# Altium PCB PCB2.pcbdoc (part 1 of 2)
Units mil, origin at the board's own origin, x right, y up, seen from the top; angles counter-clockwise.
Board outline 4920 x 2460 mil, 2 copper layers (Top Layer, Bottom Layer); 93 components, 68 nets, 331 pads, 95 vias.
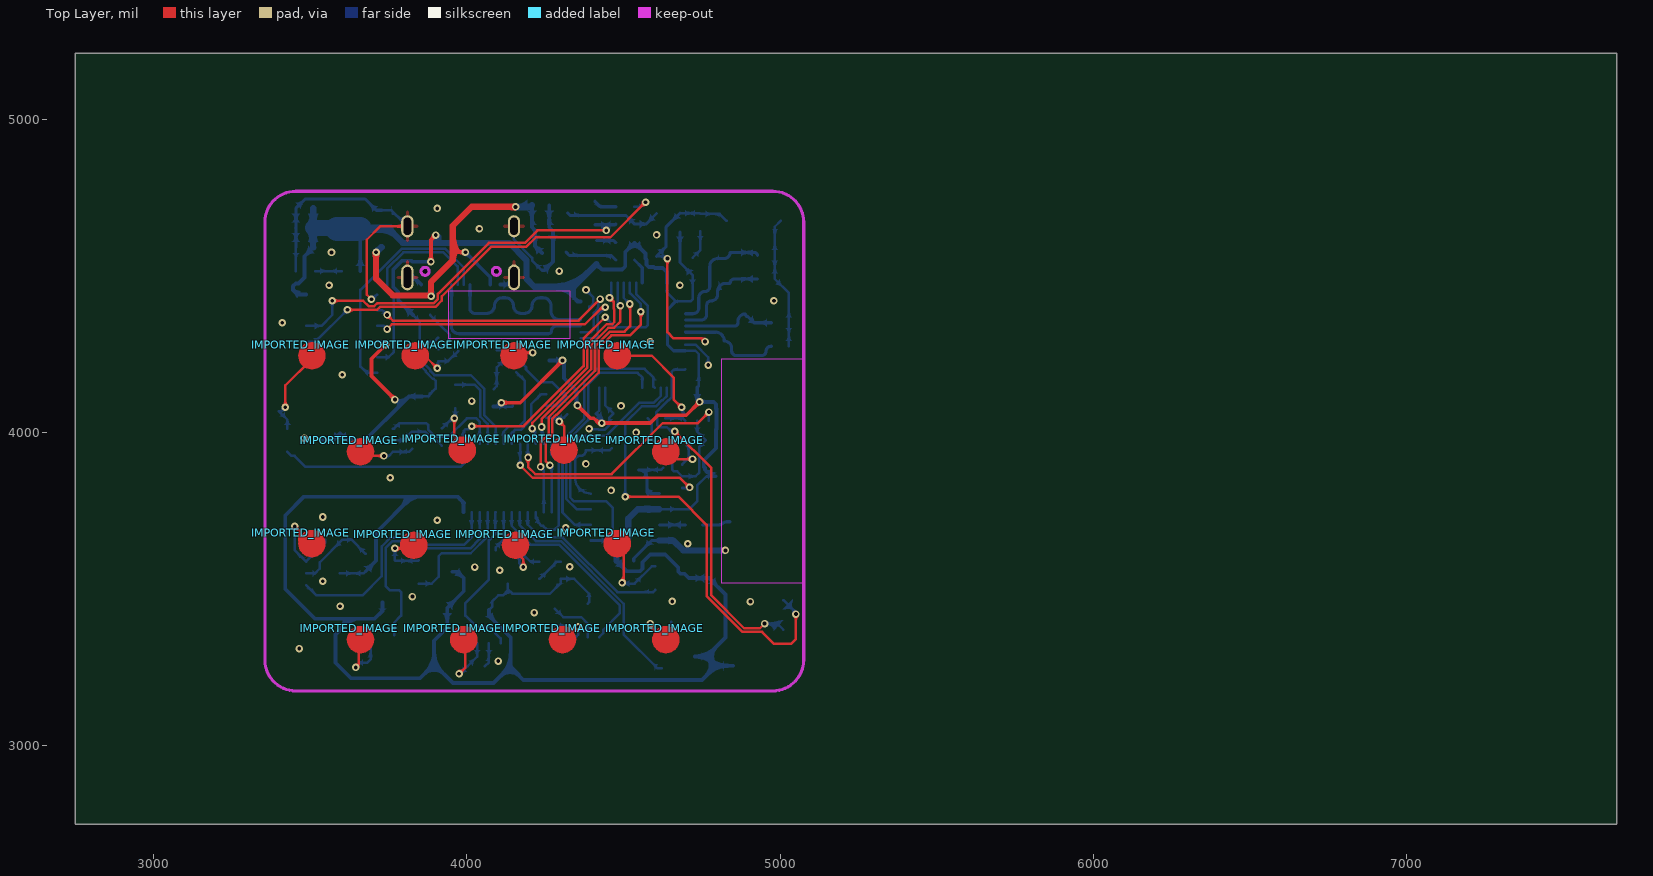
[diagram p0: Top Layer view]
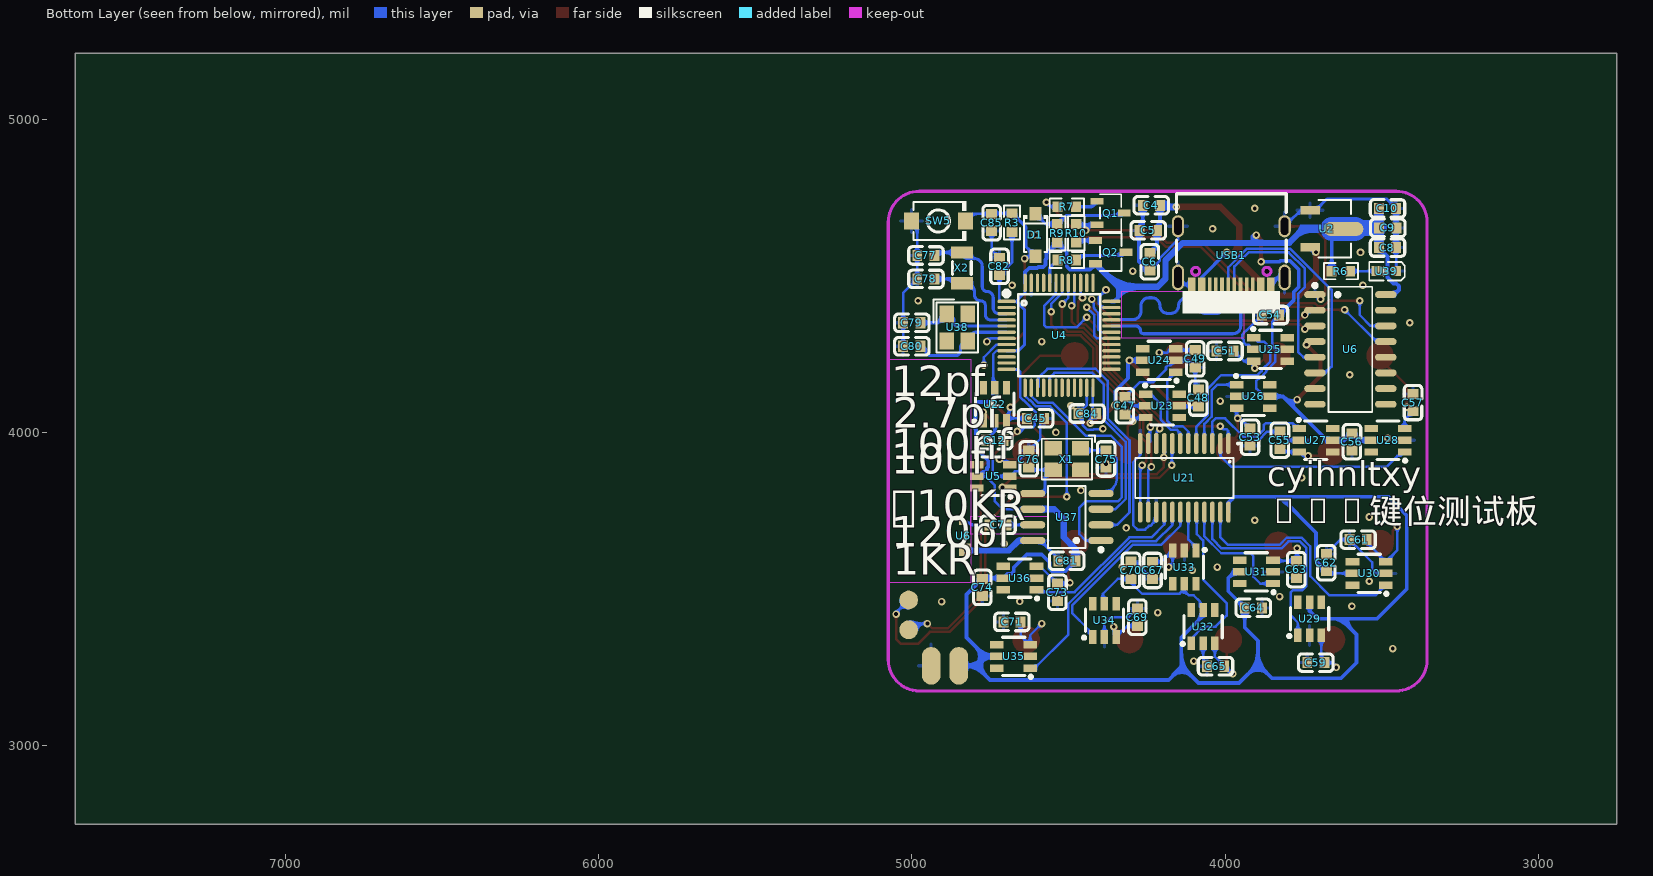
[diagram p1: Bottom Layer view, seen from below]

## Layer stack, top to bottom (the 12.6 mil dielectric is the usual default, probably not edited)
Top Layer: signal copper (thickness not stored)
Dielectric: dielectric 12.6, FR-4, Dk 4.8
Bottom Layer: signal copper (thickness not stored)

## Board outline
7670,2750 2750,2750 2750,5210 7670,5210

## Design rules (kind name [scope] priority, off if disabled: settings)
Clearance copperThickness1oz [All] p1: gap=7 ignorepadtopadclearanceinfootprint=FALSE except(4: Track-Track; 6: Track-SMDPad SMDPad-SMDPad Track-THPad SMDPad-THPad THPad-THPad Track-Via SMDPad-Via THPad-Via Via-Via SMDPad-Fill THPad-Fill Via-Fill Fill-Fill Track-Region SMDPad-Region THPad-Region Via-Region Region-Region Track-Poly SMDPad-Poly THPad-Poly Via-Poly Fill-Poly Region-Poly Poly-Poly Track-Text SMDPad-Text THPad-Text Via-Text Fill-Text Region-Text Poly-Text Text-Text; 6.9: Track-Hole SMDPad-Hole THPad-Hole Via-Hole Fill-Hole Region-Hole Poly-Hole Text-Hole Sheet-Hole; 11.8: Track-Fill Fill-Region Track-Sheet SMDPad-Sheet THPad-Sheet Via-Sheet Fill-Sheet Region-Sheet Poly-Sheet Text-Sheet)
Clearance copperThickness2oz [All] p1: gap=7 ignorepadtopadclearanceinfootprint=FALSE except(6: Track-SMDPad SMDPad-SMDPad Track-THPad SMDPad-THPad THPad-THPad Track-Via SMDPad-Via THPad-Via Via-Via SMDPad-Fill THPad-Fill Via-Fill Fill-Fill Track-Region SMDPad-Region THPad-Region Via-Region Region-Region Track-Poly SMDPad-Poly THPad-Poly Via-Poly Fill-Poly Region-Poly Poly-Poly Track-Text SMDPad-Text THPad-Text Via-Text Fill-Text Region-Text Poly-Text Text-Text; 6.9: Track-Hole SMDPad-Hole THPad-Hole Via-Hole Fill-Hole Region-Hole Poly-Hole Text-Hole Sheet-Hole; 8: Track-Track; 11.8: Track-Fill Fill-Region Track-Sheet SMDPad-Sheet THPad-Sheet Via-Sheet Fill-Sheet Region-Sheet Poly-Sheet Text-Sheet)
DiffPairsRouting differentialPair [All] p1: maxuncoupledlength=10 maxlimit=6 mostfreqgap=6 toplayer_minwidth=5 toplayer_prefwidth=10 toplayer_maxwidth=100 bottomlayer_minwidth=5 bottomlayer_prefwidth=10 bottomlayer_maxwidth=100
PasteMaskExpansion pasteMaskExpansion [All] p1:
PlaneConnect innerPlane [All] p1: planeconnectstyle=Relief reliefexpansion=20 reliefentries=4 reliefconductorwidth=10 reliefairgap=10
PolygonConnect copperRegion [All] p1: connectstyle=Relief reliefentries=4 reliefconductorwidth=10 polygonreliefangle="90 Angle" airgapwidth=10
RoutingVias viaSize [All] p1: viastyle="Through Hole" holewidth=12.0078 minholewidth=11.811 maxholewidth=248.0314 width=24.0158 minwidth=19.685 maxwidth=393.7008
SolderMaskExpansion solderMaskExpansion [All] p1: useseparateexpansions=TRUE expansion=2 expansionbottom=2
Width copperThickness1oz [All] p1: maxlimit=100 minlimit=5 preferedwidth=10
Width copperThickness2oz [All] p1: maxlimit=100 minlimit=8 preferedwidth=10

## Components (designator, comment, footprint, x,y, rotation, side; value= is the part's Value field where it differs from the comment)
C4 "CL10A106KP8NNNC" C0603 4235,4725 r180 bottom
C5 "CL10A105KB8NNNC" C0603 4245,4645 r180 bottom
C6 "CC0603KRX7R9BB104" C0603 4240,4545 r90 bottom
C7 "2.7pF(2R7) ±0.25pF 50V" C0603 4725,3705 r0 bottom
C8 "CL10A106KP8NNNC" C0603 3481.55,4590.21 r0 bottom
C9 "CL10A105KB8NNNC" C0603 3480.61,4653.08 r0 bottom
C10 "CC0603KRX7R9BB104" C0603 3481.55,4715.21 r0 bottom
C12 "CL10C101JB8NNNC" C0603 4735,3975 r180 bottom
C45 "CL10C101JB8NNNC" C0603 4605,4045 r0 bottom
C47 "CL10C101JB8NNNC" C0603 4320,4085 r270 bottom
C48 "CC0603KRX7R9BB104" C0603 4085,4110 r90 bottom
C49 "CL10C101JB8NNNC" C0603 4095,4235 r90 bottom
C51 "CL10C101JB8NNNC" C0603 4000,4260 r180 bottom
C53 "CL10C101JB8NNNC" C0603 3920,3985 r90 bottom
C54 "CC0603KRX7R9BB104" C0603 3855,4375 r0 bottom
C55 "CL10C101JB8NNNC" C0603 3825,3975 r270 bottom
C56 "CC0603KRX7R9BB104" C0603 3595,3970 r270 bottom
C57 "CL10C101JB8NNNC" C0603 3400,4095 r270 bottom
C59 "CL10C101JB8NNNC" C0603 3710,3265 r180 bottom
C61 "CL10C101JB8NNNC" C0603 3575.02,3657.66 r180 bottom
C62 "CC0603KRX7R9BB104" C0603 3676.62,3584.42 r90 bottom
C63 "CL10C101JB8NNNC" C0603 3772.44,3562.44 r90 bottom
C64 "CC0603KRX7R9BB104" C0603 3909.39,3439.79 r180 bottom
C65 "CL10C101JB8NNNC" C0603 4030.02,3253.74 r180 bottom
C67 "CL10C101JB8NNNC" C0603 4231.36,3559.69 r90 bottom
C69 "CL10C101JB8NNNC" C0603 4280,3410 r270 bottom
C70 "CC0603KRX7R9BB104" C0603 4300,3560 r90 bottom
C71 "CL10C101JB8NNNC" C0603 4680,3395 r180 bottom
C73 "CL10C101JB8NNNC" C0603 4535,3490 r90 bottom
C74 "CC0603KRX7R9BB104" C0603 4775,3505 r270 bottom
C75 "CC0603CRNPO9BN9R0" C0603 4380,3915 r270 bottom
C76 "CC0603CRNPO9BN9R0" C0603 4626.72,3915.16 r270 bottom
C77 "CL10C100JB8NNNC" C0603 4955,4565 r0 bottom
C78 "CL10C100JB8NNNC" C0603 4955,4490 r0 bottom
C79 "CL10C100JB8NNNC" C0603 5000,4350 r0 bottom
C80 "CL10C100JB8NNNC" C0603 5000,4275 r0 bottom
C81 "CC0603KRX7R9BB104" C0603 4505,3590 r180 bottom
C82 "CC0603KRX7R9BB104" C0603 4720,4530 r270 bottom
C84 "CC0603KRX7R9BB104" C0603 4440,4060 r180 bottom
C85 "CAP_0603" C0603 4745,4670 r90 bottom
D1 "1N4148W_C81598" SOD-123F_L2.7-W1.6-LS3.8-RD 4605.12,4630.39 r270 bottom
IMPORTED_IMAGE "IMPORTED_IMAGE" IMPORTED_IMAGE 3470,4280 r0 top
IMPORTED_IMAGE "IMPORTED_IMAGE" IMPORTED_IMAGE 3800,4280 r0 top
IMPORTED_IMAGE "IMPORTED_IMAGE" IMPORTED_IMAGE 4115,4280 r0 top
IMPORTED_IMAGE "IMPORTED_IMAGE" IMPORTED_IMAGE 4445,4280 r0 top
IMPORTED_IMAGE "IMPORTED_IMAGE" IMPORTED_IMAGE 3625,3975 r0 top
IMPORTED_IMAGE "IMPORTED_IMAGE" IMPORTED_IMAGE 3950,3980 r0 top
IMPORTED_IMAGE "IMPORTED_IMAGE" IMPORTED_IMAGE 4275,3980 r0 top
IMPORTED_IMAGE "IMPORTED_IMAGE" IMPORTED_IMAGE 4600,3975 r0 top
IMPORTED_IMAGE "IMPORTED_IMAGE" IMPORTED_IMAGE 4120,3675 r0 top
IMPORTED_IMAGE "IMPORTED_IMAGE" IMPORTED_IMAGE 3795,3675 r0 top
IMPORTED_IMAGE "IMPORTED_IMAGE" IMPORTED_IMAGE 4445,3680 r0 top
IMPORTED_IMAGE "IMPORTED_IMAGE" IMPORTED_IMAGE 4270,3375 r0 top
IMPORTED_IMAGE "IMPORTED_IMAGE" IMPORTED_IMAGE 3955,3375 r0 top
IMPORTED_IMAGE "IMPORTED_IMAGE" IMPORTED_IMAGE 4600,3375 r0 top
IMPORTED_IMAGE "IMPORTED_IMAGE" IMPORTED_IMAGE 3470,3680 r0 top
IMPORTED_IMAGE "IMPORTED_IMAGE" IMPORTED_IMAGE 3625,3375 r0 top
Q1 "S8050 J3Y_C2146" SOT-23-3_L3.0-W1.7-P0.95-LS2.9-BR 4365.12,4700.39 r0 bottom
Q2 "S8550-2TY 800MA" SOT-23-3_L2.9-W1.6-P1.90-LS2.8-BR 4365.12,4575.39 r0 bottom
R3 "Res_0603" R0603 4680,4670 r270 bottom
R6 "Res_0603" R0603 3630,4515 r180 bottom
R7 "0603WAF1001T5E" R0603 4505.12,4720.39 r180 bottom
R8 "0603WAF1001T5E" R0603 4505.12,4550.39 r0 bottom
R9 "Res_0603" R0603 4535.12,4635.39 r270 bottom
R10 "0603WAF1001T5E" R0603 4475.12,4635.39 r270 bottom
SW5 "TS-1088R-02526" SW-SMD_L3.9-W3.0-P4.45 4915,4675 r180 bottom
U2 "AMS1117-3.3V-JSM" SOT-89-3_L4.5-W2.5-P1.50-LS4.2-TL 3675,4650 r180 bottom
U4 "STM32F103C8T6" LQFP-48_L7.0-W7.0-P0.50-LS9.0-BL 4530,4310 r270 bottom
U5 "TTP233D-HA6" SOT-23-6_L2.9-W1.6-P0.95-LS2.8-BR 4740,3860 r180 bottom
U6 "CH340C" SOP-16_L10.0-W3.9-P1.27-LS6.0-BL 3600,4265 r270 bottom
U6 "ANT1_2.4G" ANT1_2.4G 5030,3605 r90 top
U21 "CD4067BPWG4" TSSOP-24_L7.8-W4.4-P0.65-LS6.4-BL_1 4130,3855 r0 bottom
U22 "TTP233D-HA6" SOT-23-6_L2.9-W1.6-P0.95-LS2.8-BR 4735,4090 r270 bottom
U23 "TTP233D-HA6" SOT-23-6_L2.9-W1.6-P0.95-LS2.8-BR 4200,4085 r0 bottom
U24 "TTP233D-HA6" SOT-23-6_L2.9-W1.6-P0.95-LS2.8-BR 4210,4230 r180 bottom
U25 "TTP233D-HA6" SOT-23-6_L2.9-W1.6-P0.95-LS2.8-BR 3855,4265 r0 bottom
U26 "TTP233D-HA6" SOT-23-6_L2.9-W1.6-P0.95-LS2.8-BR 3910,4115 r0 bottom
U27 "TTP233D-HA6" SOT-23-6_L2.9-W1.6-P0.95-LS2.8-BR 3710,3975 r0 bottom
U28 "TTP233D-HA6" SOT-23-6_L2.9-W1.6-P0.95-LS2.8-BR 3480,3975 r180 bottom
U29 "TTP233D-HA6" SOT-23-6_L2.9-W1.6-P0.95-LS2.8-BR 3730,3405 r270 bottom
U30 "TTP233D-HA6" SOT-23-6_L2.9-W1.6-P0.95-LS2.8-BR 3540,3550 r180 bottom
U31 "TTP233D-HA6" SOT-23-6_L2.9-W1.6-P0.95-LS2.8-BR 3900,3555 r180 bottom
U32 "TTP233D-HA6" SOT-23-6_L2.9-W1.6-P0.95-LS2.8-BR 4070,3380 r270 bottom
U33 "TTP233D-HA6" SOT-23-6_L2.9-W1.6-P0.95-LS2.8-BR 4130,3570 r90 bottom
U34 "TTP233D-HA6" SOT-23-6_L2.9-W1.6-P0.95-LS2.8-BR 4385,3400 r270 bottom
U35 "TTP233D-HA6" SOT-23-6_L2.9-W1.6-P0.95-LS2.8-BR 4675,3285 r180 bottom
U36 "TTP233D-HA6" SOT-23-6_L2.9-W1.6-P0.95-LS2.8-BR 4655,3535 r180 bottom
U37 "Ci24R1" SOIC-8_L4.9-W3.9-P1.27-LS6.0-BL 4505,3730 r90 bottom
U38 "SMD_3225-8MHz" CRYSTAL-SMD_4P-L3.2-W2.5-BL 4855,4335 r270 bottom
U39 "LED白" LED0603-RD_WHITE 3485,4515 r0 bottom
USB1 "TYPE-C16PIN" USB-C-SMD_TYPE-C16PIN 3980,4565 r0 bottom
X1 "X322516MLB4SI" OSC-SMD_4P-L3.2-W2.5-BL 4505,3915 r0 bottom
X2 "Q13FC13500004_C32346" FC-135R_L3.2-W1.5 4840,4525 r270 bottom

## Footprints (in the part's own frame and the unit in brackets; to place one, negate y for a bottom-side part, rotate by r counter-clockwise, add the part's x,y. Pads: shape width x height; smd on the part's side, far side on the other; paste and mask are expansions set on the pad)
ANT1_2.4G [mm]
  rect 0.5x0.5 smd far side: 1(2.794,4.826)
  rect 1x1 smd far side: 2(0.508,5.08)
C0603 [mm]
  rect 0.8x0.9 smd: 1(-0.7,0) 2(0.7,0)
  silkscreen extent -1.41,-0.71 1.39,0.72
CRYSTAL-SMD_4P-L3.2-W2.5-BL [mm]
  rect 1.4x1.2 smd: 1(-1.1,-0.85) 2(1.1,-0.85) 3(1.1,0.85) 4(-1.1,0.85)
  silkscreen extent -2.26,-1.91 2.03,1.68
FC-135R_L3.2-W1.5 [mm]
  rect 1x1.8 smd: 1(-1.25,0) 2(1.25,0)
  silkscreen extent -0.51,-0.76 0.51,0.76
IMPORTED_IMAGE [mil]
LED0603-RD_WHITE [mm]
  rect 0.8x0.8 smd: 1(-0.799,-0.003) 2(0.799,0.003)
  silkscreen extent -1.49,-0.75 1.39,0.76
LQFP-48_L7.0-W7.0-P0.50-LS9.0-BL [mm]
  oval 0.27x1.5 smd: 1(-2.75,-4.25) 2(-2.25,-4.25) 3(-1.75,-4.25) 4(-1.25,-4.25) 5(-0.75,-4.25) 6(-0.25,-4.25) 7(0.25,-4.25) 8(0.75,-4.25) 9(1.25,-4.25) 10(1.75,-4.25) 11(2.25,-4.25) 12(2.75,-4.25) 25(2.75,4.25) 26(2.25,4.25) 27(1.75,4.25) 28(1.25,4.25) 29(0.75,4.25) 30(0.25,4.25) 31(-0.25,4.25) 32(-0.75,4.25) 33(-1.25,4.25) 34(-1.75,4.25) 35(-2.25,4.25) 36(-2.75,4.25)
  oval 1.5x0.27 smd: 13(4.25,-2.75) 14(4.25,-2.25) 15(4.25,-1.75) 16(4.25,-1.25) 17(4.25,-0.75) 18(4.25,-0.25) 19(4.25,0.25) 20(4.25,0.75) 21(4.25,1.25) 22(4.25,1.75) 23(4.25,2.25) 24(4.25,2.75) 37(-4.25,2.75) 38(-4.25,2.25) 39(-4.25,1.75) 40(-4.25,1.25) 41(-4.25,0.75) 42(-4.25,0.25) 43(-4.25,-0.25) 44(-4.25,-0.75) 45(-4.25,-1.25) 46(-4.25,-1.75) 47(-4.25,-2.25) 48(-4.25,-2.75)
  silkscreen extent -3.59,-4.46 3.3,3.34
OSC-SMD_4P-L3.2-W2.5-BL [mm]
  rect 1.4x1.2 smd: 1(-1.1,-0.875) 2(1.1,-0.875) 3(1.1,0.875) 4(-1.1,0.875)
  silkscreen extent -2.29,-1.9 2.03,1.65
R0603 [mil]
  rect 31.75x34.02 smd: 1(-29.66,0) 2(29.66,0)
  silkscreen extent -55,-26 55,26
SOD-123F_L2.7-W1.6-LS3.8-RD [mm]
  rect 1.1x1 smd: 1(-1.735,0) 2(1.735,0)
  silkscreen extent -1.6,-1 1.38,1
SOIC-8_L4.9-W3.9-P1.27-LS6.0-BL [mm]
  oval 0.588x2.045 smd: 1(-1.905,-2.772) 2(-0.635,-2.772) 3(0.635,-2.772) 4(1.905,-2.772) 5(1.905,2.772) 6(0.635,2.772) 7(-0.635,2.772) 8(-1.905,2.772)
  silkscreen extent -2.8,-2.92 2.53,1.52
SOP-16_L10.0-W3.9-P1.27-LS6.0-BL [mm]
  oval 0.56x1.745 smd: 1(-4.445,-2.872) 2(-3.175,-2.872) 3(-1.905,-2.872) 4(-0.635,-2.872) 5(0.635,-2.872) 6(1.905,-2.872) 7(3.175,-2.872) 8(4.445,-2.872) 9(4.445,2.872) 10(3.175,2.872) 11(1.905,2.872) 12(0.635,2.872) 13(-0.635,2.872) 14(-1.905,2.872) 15(-3.175,2.872) 16(-4.445,2.872)
  silkscreen extent -5.33,-3.02 5.08,1.77
SOT-23-3_L2.9-W1.6-P1.90-LS2.8-BR [mm]
  rect 1.07x0.6 smd: 1(1.235,-0.95) 2(1.235,0.95) 3(-1.235,0)
  silkscreen extent -0.88,-1.54 0.88,1.54
SOT-23-3_L3.0-W1.7-P0.95-LS2.9-BR [mil]
  rect 40.85x20.95 smd: 1(43.36,-37.4) 2(43.36,37.4) 3(-43.36,0)
  silkscreen extent -34,-60 34,60
SOT-23-6_L2.9-W1.6-P0.95-LS2.8-BR [mm]
  rect 1.1x0.6 smd: 1(1.35,-0.95) 2(1.35,0) 3(1.35,0.95) 4(-1.35,0.95) 5(-1.35,0) 6(-1.35,-0.95)
  silkscreen extent -0.9,-1.78 1.52,1.55
SOT-89-3_L4.5-W2.5-P1.50-LS4.2-TL [mm]
  rect 1.575x0.672 smd: 1(-1.356,1.5) 3(-1.356,-1.5)
  oval 3.226x1.14 smd: 2(1.356,-0.009)
  Top Layer region: 2.283,-0.959 0.429,-0.959 0.384,-0.958 0.34,-0.954 0.296,-0.949 0.252,-0.942 0.208,-0.933 0.165,-0.921 0.123,-0.908 0.081,-0.893 0.04,-0.875 0,-0.856 -0.04,-0.835 -0.078,-0.812 -0.115,-0.787 -0.151,-0.761 -0.185,-0.733 -0.219,-0.704 -0.251,-0.672 -0.281,-0.64 -0.31,-0.606 -0.337,-0.571 -0.362,-0.534 -0.386,-0.496 -0.408,-0.458 -0.428,-0.418 -0.447,-0.339 -2.144,-0.339 -2.144,0.321 -0.447,0.321 -0.428,0.401 -0.408,0.44 -0.386,0.479 -0.362,0.517 -0.337,0.553 -0.31,0.589 -0.281,0.623 -0.251,0.655 -0.219,0.686 -0.185,0.716 -0.151,0.744 -0.115,0.77 -0.078,0.795 -0.04,0.818 0,0.839 0.04,0.858 0.081,0.875 0.123,0.891 0.165,0.904 0.208,0.915 0.252,0.925 0.296,0.932 0.34,0.937 0.384,0.94 0.429,0.941 2.283,0.941 2.328,0.94 2.372,0.937 2.416,0.932 2.46,0.925 2.504,0.915 2.547,0.904 2.589,0.891 2.631,0.875 2.672,0.858 2.712,0.839 2.752,0.818 2.79,0.795 2.827,0.77 2.863,0.744 2.898,0.716 2.931,0.686 2.963,0.655 2.993,0.623 3.022,0.589 3.049,0.553 3.075,0.517 3.098,0.479 3.12,0.44 3.14,0.401 3.159,0.36 3.175,0.319 3.189,0.277 3.202,0.234 3.212,0.19 3.22,0.147 3.227,0.103 3.231,0.058 3.233,0.014 3.233,-0.031 3.231,-0.075 3.227,-0.12 3.22,-0.164 3.212,-0.208 3.202,-0.251 3.189,-0.294 3.175,-0.336 3.159,-0.377 3.14,-0.418 3.12,-0.458 3.098,-0.496 3.075,-0.534 3.049,-0.571 3.022,-0.606 2.993,-0.64 2.963,-0.672 2.931,-0.704 2.898,-0.733 2.863,-0.761 2.827,-0.787 2.79,-0.812 2.752,-0.835 2.712,-0.856 2.672,-0.875 2.631,-0.893 2.589,-0.908 2.547,-0.921 2.504,-0.933 2.46,-0.942 2.416,-0.949 2.372,-0.954 2.328,-0.958
  silkscreen extent -0.69,-2.33 1.96,2.33
SW-SMD_L3.9-W3.0-P4.45 [mm]
  rect 1.23x1.36 smd: 1(-2.185,0) 2(2.185,0)
  silkscreen extent -2.03,-1.62 2.25,1.62
TSSOP-24_L7.8-W4.4-P0.65-LS6.4-BL_1 [mm]
  oval 0.364x1.71 smd: 1(-3.575,-2.78) 2(-2.925,-2.78) 3(-2.275,-2.78) 4(-1.625,-2.78) 5(-0.975,-2.78) 6(-0.325,-2.78) 7(0.325,-2.78) 8(0.975,-2.78) 9(1.625,-2.78) 10(2.275,-2.78) 11(2.925,-2.78) 12(3.575,-2.78) 13(3.575,2.78) 14(2.925,2.78) 15(2.275,2.78) 16(1.625,2.78) 17(0.975,2.78) 18(0.325,2.78) 19(-0.325,2.78) 20(-0.975,2.78) 21(-1.625,2.78) 22(-2.275,2.78) 23(-2.925,2.78) 24(-3.575,2.78)
  silkscreen extent -4.42,-2.85 3.98,1.62
USB-C-SMD_TYPE-C16PIN [mm]
  oval 1x2.1 hole 0.6 slot 1.7 at 90 deg: 1(-4.32,1.787) 2(4.32,1.787)
  oval 1x1.8 hole 0.6 slot 1.4 at 90 deg: 3(-4.32,-2.362) 4(4.32,-2.362)
  rect 0.6x1.15 smd: A1B12(-3.2,2.362) A4B9(-2.4,2.362) B1A12(3.2,2.362) B4A9(2.4,2.362)
  rect 0.3x1.15 smd: A5(-1.25,2.362) A6(-0.25,2.362) A7(0.25,2.362) A8(-1.75,2.362) B5(1.75,2.362) B6(0.75,2.362) B7(-0.75,2.362) B8(1.25,2.362)
  Multi-Layer board cut-out: 3.215,1.288 3.183,1.147 3.093,1.034 2.962,0.971 2.818,0.971 2.687,1.034 2.597,1.147 2.565,1.288 2.565,1.288 2.597,1.429 2.687,1.542 2.818,1.605 2.962,1.605 3.093,1.542 3.183,1.429 3.215,1.288
  Multi-Layer board cut-out: -2.565,1.288 -2.611,1.128 -2.729,1.012 -2.89,0.969 -3.051,1.012 -3.169,1.128 -3.215,1.288 -3.215,1.288 -3.169,1.448 -3.051,1.564 -2.89,1.607 -2.729,1.564 -2.611,1.448 -2.565,1.288
  Multi-Layer keep-out circle w0.254: c2.89,1.288 r0.325
  Multi-Layer keep-out circle w0.254: c-2.89,1.288 r0.325
  silkscreen extent -4.45,-5 4.45,0.52

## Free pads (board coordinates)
  oval 60x120 smd far side: 1(4850,3255) 1(4938.09,3255)
  round 60 smd far side: 1(5010,3370) 1(5010,3465)

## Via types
v1: diameter 24.02, hole 12.01, Top Layer to Bottom Layer, 95 vias

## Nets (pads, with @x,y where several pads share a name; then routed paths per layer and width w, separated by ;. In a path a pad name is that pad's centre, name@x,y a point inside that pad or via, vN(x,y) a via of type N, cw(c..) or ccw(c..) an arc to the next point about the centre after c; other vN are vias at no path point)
$C7_1: C7.1 U37.7 | length 83.3
  Bottom Layer w10: U37.7@4614.15,3705 C7.1@4697.44,3705
$C7_2: C7.2 U6.1@4840,3715 | length 89.7
  Bottom Layer w10: C7.2@4752.56,3705 4803.66,3705 ccw(c4803.66,3724.03) 4807.61,3705.41 ccw(c4803.66,3724.03) 4812.06,3706.95 ccw(c4803.66,3724.03) 4817.12,3710.57 cw(c4833.56,3682.27) 4833.56,3715 U6.1@4840,3715
$C75_1: C75.1 U37.4 X1.1 | length 272.2
  Bottom Layer w8: U37.4@4395.85,3805 cw(c4395.85,3855.85) 4345,3855.85 4345,3910 cw(c4360,3910) 4360,3925 4362.44,3925 ccw(c4362.44,3942.56) C75.1@4380,3942.56 4454.8,3942.56 X1.1@4461.69,3949.45
$C76_2: C76.2 U37.5 X1.3 | length 204.8
  Bottom Layer w8: X1.3@4548.31,3880.55 4619.67,3880.55 C76.2@4626.72,3887.6
  Bottom Layer w10: X1.3@4548.31,3880.55 cw(c4548.31,3853.86) 4575,3853.86 4575,3820 ccw(c4590,3820) 4590,3805 U37.5@4614.15,3805
$C77_1: C77.1 U4.3 X2.1 | length 388.7
  Bottom Layer w10: U4.3@4697.32,4378.9 4721.47,4378.9 ccw(c4721.47,4397.43) 4740,4397.43 4740,4430 cw(c4760,4430) 4760,4450 ccw(c4760,4465) 4775,4465 4775,4530 cw(c4800,4530) 4800,4555 4820.79,4555 ccw(c4820.79,4574.22) X2.1@4840.01,4574.22 4918.23,4574.22 cw(c4918.23,4565) C77.1@4927.44,4565
$C78_1: C78.1 U4.4 X2.2 | length 321.8
  Bottom Layer w10: U4.4@4697.32,4359.21 4748.89,4359.21 ccw(c4748.89,4375.32) 4765,4375.32 4765,4405 cw(c4780,4405) 4780,4420 ccw(c4780,4440) 4800,4440 4800,4450 cw(c4825.78,4450) 4825.78,4475.78 X2.2@4840.01,4475.78 cw(c4854.22,4475.78) 4854.22,4490 C78.1@4927.44,4490
$C79_1: C79.1 U4.5 U38.1 | length 312.4
  Bottom Layer w10: U4.5@4697.32,4339.53 4854.53,4339.53 ccw(c4854.53,4350) 4865,4350 4865,4354.85 cw(c4888.47,4354.85) U38.1@4888.47,4378.31 ccw(c4896.77,4378.31) 4896.77,4370 4916.77,4350 C79.1@4972.44,4350
$C80_1: C80.1 U4.6 U38.3 | length 338.7
  Bottom Layer w10: U4.6@4697.32,4319.84 cw(c4697.48,4319.84) 4697.48,4320 4793.23,4320 cw(c4793.23,4291.69) U38.3@4821.53,4291.69 cw(c4821.53,4268.23) 4845,4268.23 4845,4260 ccw(c4860,4260) 4860,4245 4940,4245 ccw(c4940,4260) 4955,4260 cw(c4970,4260) 4970,4275 C80.1@4972.44,4275
$D1_1: D1.1 Q1.3 R9.1 | length 311.9
  Bottom Layer w10: Q1.3@4321.76,4700.39 4329.75,4692.4 4507.77,4692.4 R9.1@4535.12,4665.05 4571.47,4665.05 D1.1@4605.12,4698.7
$Q1_1: Q1.1 R7.2 | length 74.2
  Bottom Layer w10: Q1.1@4408.48,4737.79 4425.88,4720.39 R7.2@4475.46,4720.39
$Q1_2: Q1.2 R10.1 U6.14 | length 1227.5
  Top Layer w8: v1(3570,4420) 3668.9,4420 3685.89,4403.01 3704.11,4403.01 3714.11,4413.01 3894.62,4413.01 3907.5,4425.89 3907.5,4442.5 4070,4605 4185,4605 4225,4645 v1(4445,4645)
  Bottom Layer w8: U6.14@3486.91,4340 3535,4340 3570,4375 v1(3570,4420) ; Q1.2@4427.01,4662.99 v1(4445,4645)
  Bottom Layer w10: Q1.2@4408.48,4662.99 4427.01,4662.99 4473.06,4662.99 R10.1@4475.12,4665.05
$Q2_1: Q2.1 R10.2 | length 64.3
  Bottom Layer w10: Q2.1@4413.74,4612.79 4468.06,4612.79 R10.2@4475.12,4605.73
$Q2_3: Q2.3 R8.1 | length 169.3
  Bottom Layer w10: Q2.3@4316.49,4575.39 4326.89,4565 4460.85,4565 R8.1@4475.46,4550.39
$R6_2: R6.2 U39.2 | length 83.9
  Bottom Layer w8: U39.2@3516.47,4514.86 3516.61,4515 R6.2@3600.34,4515
$R7_1: R7.1 U6.13 | length 1317.1
  Top Layer w8: v1(3618.51,4391.49) 3680.41,4391.49 3680.91,4390.99 3709.09,4390.99 3709.59,4391.49 3713.48,4391.49 3722.98,4400.99 3899.6,4400.99 3919.52,4420.91 3919.52,4434.52 4077.98,4592.98 4189.98,4592.98 4220,4623.01 4458.01,4623.01 v1(4570,4735)
  Bottom Layer w8: U6.13@3486.91,4290 3517.02,4290 v1(3618.51,4391.49) ; R7.1@4534.78,4720.39 4555.39,4720.39 v1(4570,4735)
$U37_1: U4.14 U37.1 | length 856.1
  Bottom Layer w8: U37.1@4395.85,3655 4445,3655 4465,3675 4465,3760 4445,3780 4341.99,3780 4329.03,3792.96 4329.03,3954.03 4364.8,3989.8 4444.95,3989.8 4550.14,4095 4597.07,4095 4618.58,4116.51 U4.14@4618.58,4142.68
$U37_2: U4.15 U37.2 | length 837.8
  Bottom Layer w8: U37.2@4395.85,3705 4345,3705 4305,3745 4305,3974.89 4374.69,4044.58 4374.69,4164.9 4412.81,4203.02 4566.98,4203.02 4595,4175 4595,4146.58 U4.15@4598.9,4142.68
$U37_3: U4.17 U37.3 | length 714
  Bottom Layer w8: U37.3@4395.85,3755 4350,3755 4317.02,3787.98 4317.02,3969.91 4386.71,4039.6 4386.71,4153.51 4423.2,4190 4545,4190 4560,4175 4560,4143.15 U4.17@4559.53,4142.68
+5V: C4.2 C5.2 C6.2 U2.3 USB1.A4B9 USB1.B4A9 | length 1229.2
  Top Layer w12: 3955,4596.55 3976.55,4575 v1(3995,4575)
  Top Layer w20: v1(3710,4575) 3710,4490 3762.69,4437.31 3883.2,4437.31 v1(3885.51,4435) 3885.51,4480.51 3955,4550 3955,4596.55 3955,4660 4015,4720 v1(4155,4720)
  Bottom Layer w12: v1(3995,4575) 4074.49,4495.51 USB1.B4A9@4074.49,4471.99 ; C4.2@4207.44,4725 4207.44,4655 C5.2@4217.44,4645 4217.44,4595.12 C6.2@4240,4572.56
  Bottom Layer w20: v1(3710,4575) 3725.95,4590.94 U2.3@3728.39,4590.94 ; v1(3885.51,4435) USB1.A4B9@3885.51,4471.99 ; v1(4155,4720) 4202.44,4720 C4.2@4207.44,4725
A: U4.39 U21.10 | length 645.4
  Top Layer w8: v1(4208.3,4012.2) 4208.3,4030.38 4384.72,4206.8 4384.72,4284.42 4446.35,4346.05 4464.49,4346.05 4470.14,4351.7 4470.14,4393.2 4468.01,4395.34 4468.01,4416.99 v1(4455,4430)
  Bottom Layer w8: v1(4208.3,4012.2) 4218.55,4001.95 4218.55,3965.47 U21.10@4219.57,3964.45 ; v1(4455,4430) 4461.1,4436.1 U4.39@4461.1,4477.32
B: U4.40 U21.11 | length 634.7
  Top Layer w8: v1(4238.3,4017.29) 4238.3,4043.39 4396.73,4201.82 4396.73,4279.44 4451.32,4334.03 4470,4334.03 4490,4354.03 v1(4490,4404.45)
  Bottom Layer w8: v1(4238.3,4017.29) 4238.3,3971.31 U21.11@4245.16,3964.45 ; U4.40@4480.79,4477.32 4480.79,4413.66 v1(4490,4404.45)
BOOT0: R8.2 U4.44 | length 83.3
  Bottom Layer w10: R8.2@4534.78,4550.39 4559.53,4525.64 U4.44@4559.53,4477.32
C: U4.41 U21.14 | length 890.3
  Top Layer w8: v1(4235,3890) 4235,3969.22 4260.99,3995.21 4260.99,4049.09 4408.75,4196.84 4408.75,4274.46 4456.3,4322.02 4503.45,4322.02 4520.66,4339.22 4520.66,4393.85 4520,4394.5 v1(4520,4410)
  Bottom Layer w8: v1(4235,3890) 4245.16,3879.84 U21.14@4245.16,3745.55 ; U4.41@4500.47,4477.32 4500.47,4429.53 v1(4520,4410)
D: U4.42 U21.13 | length 915.5
  Top Layer w8: v1(4265,3895) 4250.84,3909.16 4250.84,3968.07 4273.01,3990.24 4273.01,4044.11 4285.89,4056.99 4286.99,4056.99 4420.76,4190.76 4420.76,4269.49 4461.28,4310 4520,4310 4555,4345 v1(4555,4385)
  Bottom Layer w8: v1(4265,3895) 4270.75,3889.25 U21.13@4270.75,3745.55 ; U4.42@4520.16,4477.32 4520.16,4444.84 4555,4410 v1(4555,4385)
D+1: U4.33 USB1.B6 | length 572.3
  Bottom Layer w10: USB1.B6@4009.53,4471.99 4009.53,4395.47 ccw(c4025,4395.47) 4025,4380 4063.14,4380 ccw(c4063.14,4405) 4088.14,4405 cw(c4113.14,4405) 4113.14,4430 4123.14,4430 cw(c4123.14,4405) 4148.14,4405 ccw(c4173.14,4405) 4173.14,4380 4183.14,4380 ccw(c4183.14,4405) 4208.14,4405 cw(c4233.14,4405) 4233.14,4430 4243.14,4430 cw(c4243.14,4405) 4268.14,4405 4268.14,4386.86 ccw(c4295,4386.86) 4295,4360 4361.89,4360 cw(c4361.89,4359.21) U4.33@4362.68,4359.21
D+2: U6.5 USB1.A6 | length 659.3
  Bottom Layer w8: U6.5@3713.09,4240 3750,4240 3766.99,4256.99 3766.99,4441.96 3745,4463.95 3745,4523.01 3796.96,4574.97 3925.03,4574.97 3970.16,4529.84 USB1.A6@3970.16,4471.99
D-1: U4.32 USB1.B7 | length 573.3
  Bottom Layer w10: USB1.B7@3950.47,4471.99 3950.47,4385.47 cw(c3950,4385.47) 3950,4385 3950,4339.38 ccw(c3974.26,4339.38) 3953.84,4326.28 ccw(c3974.26,4339.38) 3974.26,4315.12 4260.12,4315.12 ccw(c4260.12,4325) 4270,4325 cw(c4284.53,4325) 4284.53,4339.53 U4.32@4362.68,4339.53
D-2: U6.6 USB1.A7 | length 770.8
  Bottom Layer w8: U6.6@3713.09,4190 3680,4190 3660,4210 3660,4455 3791.98,4586.98 3930.01,4586.98 3989.84,4527.15 USB1.A7@3989.84,4471.99
GND: 
NRST: C85.2 D1.2 R3.1 SW5.2 U4.7 | length 799.9
  Top Layer w8: v1(4640,4555) 4640,4320 4660,4300 4750,4300 v1(4760,4290)
  Bottom Layer w8: D1.2@4605.12,4562.09 4632.91,4562.09 v1(4640,4555) ; R3.1@4680,4699.66 4742.9,4699.66 C85.2@4745,4697.56 4806.42,4697.56 SW5.2@4828.98,4675 ; U4.7@4697.32,4300.16 4749.84,4300.16 v1(4760,4290)
  Bottom Layer w10: D1.2@4605.12,4562.09 4635,4591.97 4635,4654.66 R3.1@4680,4699.66
O: U4.43 U21.1 | length 996.7
  Top Layer w8: v1(4015,4020) 4180.93,4020 4372.7,4211.77 4372.7,4299.17 v1(4441.57,4368.04)
  Bottom Layer w8: U21.1@3989.25,3964.45 3990,3965.2 3990,4005 3995.66,4010.66 4005.66,4010.66 v1(4015,4020) ; v1(4441.57,4368.04) 4474.61,4335 4570,4335 4576.99,4341.99 4576.99,4405 4539.84,4442.15 U4.43@4539.84,4477.32
P1: C45.2 U22.3 | length 389.6
  Top Layer w8: 4510,4245 4590,4245 4660,4175 4660,4105 v1(4685,4080)
  Bottom Layer w8: C45.2@4632.56,4045 U22.3@4689.45,4045 ; v1(4685,4080) 4689.45,4075.55 U22.3@4689.45,4045 ; U22.3@4697.6,4036.85 U22.3@4689.45,4045
P2: C12.2 U5.3 | length 156.7
  Top Layer w8: 4665,3915 v1(4720,3915)
  Bottom Layer w8: U5.3@4686.85,3897.4 4704.45,3915 ; C12.2@4707.44,3975 4707.44,3917.99 4704.45,3915 ; v1(4720,3915) 4704.45,3915
P3: C47.2 U23.3 | length 152.5
  Top Layer w8: v1(4295,4035) 4310,4020 4310,3980
  Bottom Layer w8: U23.3@4253.15,4047.6 4279.83,4047.6 ; v1(4295,4035) 4292.43,4035 4279.83,4047.6 ; C47.2@4320,4057.44 4310.16,4047.6 4279.83,4047.6
P4: C49.2 U24.3 | length 152.1
  Top Layer w8: 4180,4255 v1(4210,4255)
  Bottom Layer w8: C49.2@4095,4262.56 4152.01,4262.56 U24.3@4156.85,4267.4 4172.6,4267.4 4185,4255 v1(4210,4255)
P5: C51.2 U25.3 | length 181.1
  Top Layer w8: 3840,4240 3870,4240 v1(3905,4205)
  Bottom Layer w8: v1(3905,4205) 3908.15,4208.15 U25.3@3908.15,4227.6 3940.04,4227.6 C51.2@3972.44,4260
P6: C53.2 U26.3 | length 166.7
  Top Layer w8: v1(3960,4045) 3960,3990 3975,3975
  Bottom Layer w8: C53.2@3920,4012.56 v1@3960,4052.56 ; v1(3960,4045) v1@3960,4052.56 ; U26.3@3963.15,4077.6 3963.15,4055.71 v1@3960,4052.56
P7: C55.2 U27.3 | length 146.4
  Top Layer w8: 3690,3930 3695,3925 v1(3735,3925)
  Bottom Layer w8: v1(3735,3925) 3750.55,3925 U27.3@3763.15,3937.6 3815.16,3937.6 C55.2@3825,3947.44
P8: C57.2 U28.3 | length 281.6
  Top Layer w8: v1(3420,4080) 3420,4150 3505,4235
  Bottom Layer w8: v1(3420,4080) 3407.44,4067.44 C57.2@3400,4067.44 3426.85,4040.59 U28.3@3426.85,4012.4
P9: C61.2 U30.3 | length 323.9
  Top Layer w8: v1(3450,3700) 3465,3685 3465,3655 3500,3620
  Bottom Layer w8: v1(3450,3700) 3450,3624.25 U30.3@3486.85,3587.4 3547.46,3648.01 C61.2@3547.46,3657.66
P10: C59.2 U29.3 | length 218.9
  Top Layer w8: v1(3645,3250) 3655,3260 3655,3330
  Bottom Layer w8: v1(3645,3250) 3660,3265 C59.2@3682.44,3265 3692.6,3275.16 U29.3@3692.6,3351.85
P11: C63.2 U31.3 | length 161.4
  Top Layer w8: v1(3770,3630) 3815,3630
  Bottom Layer w8: v1(3770,3630) 3770,3592.44 C63.2@3772.44,3590 3844.45,3590 U31.3@3846.85,3592.4
P12: C65.2 U32.3 | length 211.2
  Top Layer w8: v1(3975,3230) 3995,3250 3995,3310
  Bottom Layer w8: v1(3975,3230) 3978.73,3230 C65.2@4002.46,3253.74 4032.6,3283.87 U32.3@4032.6,3326.85
P13: C67.2 U33.3 | length 183.4
  Top Layer w8: 4165,3610 4180,3595 v1(4180,3570)
  Bottom Layer w8: v1(4180,3570) 4167.4,3582.6 U33.3@4167.4,3623.15 4203.3,3587.25 C67.2@4231.36,3587.25
P14: C69.2 U34.3 | length 146.8
  Top Layer w8: 4335,3360 v1(4355,3380)
  Bottom Layer w8: C69.2@4280,3382.44 4312.01,3382.44 U34.3@4347.6,3346.85 4355,3354.25 v1(4355,3380)
P15: C71.2 U35.3 | length 213.5
  Top Layer w8: v1(4585,3390) 4585,3380 4610,3355
  Bottom Layer w8: v1(4585,3390) 4621.85,3353.15 U35.3@4621.85,3322.4 4652.44,3352.99 C71.2@4652.44,3395
P16: C73.2 U36.3 | length 232.6
  Top Layer w8: v1(4495,3520) 4500,3525 4500,3620
  Bottom Layer w8: v1(4495,3520) 4497.44,3517.56 C73.2@4535,3517.56 4589.84,3572.4 U36.3@4601.85,3572.4
RX: U4.31 U6.2@3713.09,4390 | length 905.6
  Top Layer w8: v1(3745,4375) 3762.98,4357.02 4356.36,4357.02 v1(4425,4425.66)
  Bottom Layer w8: U6.2@3713.09,4390 3730,4390 v1(3745,4375) ; U4.31@4362.68,4319.84 4396.84,4319.84 4404.84,4327.84 4404.84,4381.9 4417,4394.06 4417,4397 4419.76,4399.76 4419.76,4412.35 4425,4417.59 v1(4425,4425.66)
T1: U21.9 U22.1 | length 772
  Top Layer w8: v1(4195,3920) 4195,3890 4217.98,3867.02 4462.02,3867.02 4625,4030 4737.4,4030 v1(4772.4,4065)
  Bottom Layer w8: U21.9@4193.98,3964.45 4193.98,3921.02 v1(4195,3920) ; U22.1@4772.4,4036.85 v1(4772.4,4065)
T2: U5.1 U21.8 | length 664.6
  Top Layer w8: v1(4170,3895) 4210,3855 4680,3855 v1(4710.66,3824.34)
  Bottom Layer w8: U21.8@4168.39,3964.45 4170,3962.84 v1(4170,3895) ; U5.1@4686.85,3822.6 4708.91,3822.6 v1(4710.66,3824.34)
T3: U21.7 U23.1 | length 224.6
  Bottom Layer w8: U21.7@4142.8,3964.45 4142.8,3997.8 4153.1,4008.1 4173.1,4008.1 4205,4040 4205,4090 4237.4,4122.4 U23.1@4253.15,4122.4
T4: U21.6 U24.1 | length 286.5
  Bottom Layer w8: U21.6@4117.2,3964.45 4117.2,4002.2 4135.11,4020.11 4166.95,4020.11 4185,4038.17 4185,4164.45 U24.1@4156.85,4192.6
T5: U21.5 U25.1 | length 538.1
  Bottom Layer w8: U25.1@3908.15,4302.4 3895.75,4290 3875,4290 3855,4270 3855,4226.94 3883.01,4198.93 3883.01,4195.89 3895.89,4183.01 4011.99,4183.01 4055,4140 4055,4055 4091.61,4018.39 U21.5@4091.61,3964.45
T6: U21.4 U26.1 | length 266.5
  Bottom Layer w8: U26.1@3963.15,4152.4 4024.59,4152.4 4042.98,4134 4042.98,4050.02 4066.02,4026.99 U21.4@4066.02,3964.45
T7: U21.3 U27.1 | length 410
  Bottom Layer w8: U27.1@3763.15,4012.4 3767.4,4012.4 3785,4030 3870,4030 3875.66,4024.34 3875.66,4009.32 3898.15,3986.83 3941.85,3986.83 4000.02,4045 4030,4045 4040.66,4034.34 4040.66,3964.68 U21.3@4040.43,3964.45
T8: U21.2 U28.1 | length 661.9
  Bottom Layer w8: U28.1@3426.85,3937.6 3439.45,3925 3450,3925 3485,3890 3980,3890 4015,3925 4015,3964.29 U21.2@4014.84,3964.45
